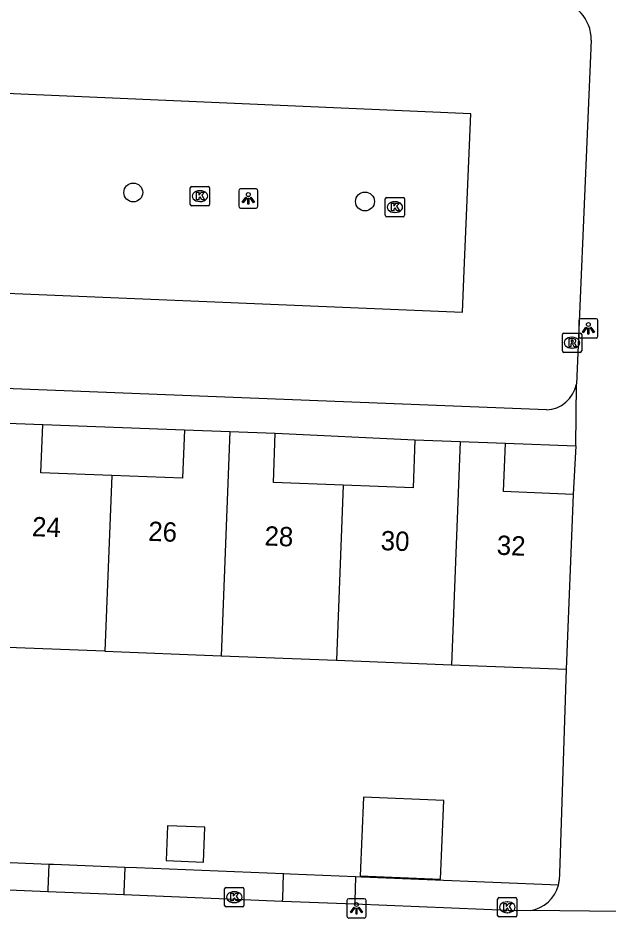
# Model space of a CAD drawing. Extents: x 160787 to 161428, y 386828 to 387483.
# Drawn here: x 161073.29 to 161103.85, y 387265 to 387311.59 of the extents above; entities that cross this region are included whole.
import ezdxf

# ---------------------------------------------------------------- set-up
doc = ezdxf.new("R2010")
doc.units = 0
for name, color, linetype in [('IMGEO_Boom', 7, 'Continuous'), ('IMGEO_Groenvoorziening', 7, 'Continuous'), ('IMGEO_Kolk', 7, 'Continuous'), ('IMGEO_Lichtpunt', 7, 'Continuous'), ('IMGEO_Pand', 7, 'Continuous'), ('IMGEO_Pand_nummerreeks', 7, 'Continuous'), ('IMGEO_Rioolput', 7, 'Continuous'), ('IMGEO_Voetpad_open', 7, 'Continuous')]:
    doc.layers.add(name, color=color, linetype=linetype)

msp = doc.modelspace()

# ---------------------------------------------------------------- linework, layer by layer
at = {"layer": 'IMGEO_Boom'}
for centre in [(161079.26, 387302.556), (161091.262, 387302.089)]:
    msp.add_circle(centre, 0.489, dxfattribs=at)
at = {"layer": 'IMGEO_Groenvoorziening'}
for points in [[(161074.883, 387267.773), (161070.863, 387267.936)], [(161087.049, 387267.279), (161079.434, 387267.588), (161078.824, 387267.613)], [(161101.28, 387266.701), (161091.074, 387267.115), (161090.777, 387267.127)]]:
    msp.add_lwpolyline(points, dxfattribs=at)
at = {"layer": 'IMGEO_Kolk'}
for p, q in [((161082.286, 387302.867), (161083.138, 387302.867)), ((161082.211, 387301.941), (161082.211, 387302.793)), ((161082.699, 387302.647), (161082.724, 387302.647)), ((161083.212, 387302.793), (161083.212, 387301.941)), ((161082.722, 387302.087), (161082.697, 387302.087)), ((161092.311, 387301.373), (161092.311, 387302.225)), ((161092.386, 387302.299), (161093.238, 387302.299)), ((161092.799, 387302.079), (161092.824, 387302.079)), ((161093.312, 387302.225), (161093.312, 387301.373)), ((161083.138, 387301.867), (161082.286, 387301.867)), ((161092.822, 387301.519), (161092.797, 387301.519)), ((161093.238, 387301.299), (161092.386, 387301.299)), ((161083.992, 387265.653), (161083.992, 387266.505)), ((161084.067, 387266.579), (161084.919, 387266.579)), ((161084.993, 387266.505), (161084.993, 387265.653)), ((161084.48, 387266.359), (161084.505, 387266.359)), ((161098.209, 387266.053), (161099.061, 387266.053)), ((161084.919, 387265.579), (161084.067, 387265.579)), ((161084.503, 387265.799), (161084.478, 387265.799)), ((161098.134, 387265.127), (161098.134, 387265.979)), ((161098.622, 387265.833), (161098.647, 387265.833)), ((161099.135, 387265.979), (161099.135, 387265.127)), ((161098.645, 387265.273), (161098.62, 387265.273)), ((161099.061, 387265.053), (161098.209, 387265.053))]:
    msp.add_line(p, q, dxfattribs=at)
for points in [[(161082.286, 387302.867), (161083.138, 387302.867)], [(161082.211, 387301.941), (161082.211, 387302.793)], [(161082.532, 387302.567), (161082.655, 387302.567), (161082.655, 387302.416), (161082.785, 387302.567), (161082.949, 387302.567), (161082.803, 387302.416), (161082.956, 387302.167), (161082.804, 387302.167), (161082.719, 387302.331), (161082.655, 387302.264), (161082.655, 387302.167), (161082.532, 387302.167), (161082.532, 387302.567)], [(161083.212, 387302.793), (161083.212, 387301.941)], [(161092.311, 387301.373), (161092.311, 387302.225)], [(161092.386, 387302.299), (161093.238, 387302.299)], [(161092.632, 387301.999), (161092.755, 387301.999), (161092.755, 387301.848), (161092.885, 387301.999), (161093.049, 387301.999), (161092.903, 387301.848), (161093.056, 387301.599), (161092.904, 387301.599), (161092.819, 387301.763), (161092.755, 387301.696), (161092.755, 387301.599), (161092.632, 387301.599), (161092.632, 387301.999)], [(161093.312, 387302.225), (161093.312, 387301.373)], [(161083.138, 387301.867), (161082.286, 387301.867)], [(161093.238, 387301.299), (161092.386, 387301.299)], [(161083.992, 387265.653), (161083.992, 387266.505)], [(161084.067, 387266.579), (161084.919, 387266.579)], [(161084.993, 387266.505), (161084.993, 387265.653)], [(161084.313, 387266.279), (161084.436, 387266.279), (161084.436, 387266.128), (161084.566, 387266.279), (161084.73, 387266.279), (161084.584, 387266.128), (161084.737, 387265.879), (161084.585, 387265.879), (161084.5, 387266.043), (161084.436, 387265.976), (161084.436, 387265.879), (161084.313, 387265.879), (161084.313, 387266.279)], [(161098.209, 387266.053), (161099.061, 387266.053)], [(161084.919, 387265.579), (161084.067, 387265.579)], [(161098.134, 387265.127), (161098.134, 387265.979)], [(161098.455, 387265.753), (161098.578, 387265.753), (161098.578, 387265.602), (161098.708, 387265.753), (161098.872, 387265.753), (161098.726, 387265.602), (161098.879, 387265.353), (161098.727, 387265.353), (161098.642, 387265.517), (161098.578, 387265.45), (161098.578, 387265.353), (161098.455, 387265.353), (161098.455, 387265.753)], [(161099.135, 387265.979), (161099.135, 387265.127)], [(161099.061, 387265.053), (161098.209, 387265.053)]]:
    msp.add_lwpolyline(points, dxfattribs=at)
for centre, start, end in [((161082.288, 387302.791), 91.552, 178.448), ((161082.288, 387302.791), 91.552, 178.448), ((161083.136, 387302.791), 1.552, 88.448), ((161083.136, 387302.791), 1.552, 88.448), ((161082.288, 387301.943), 181.552, 268.448), ((161082.288, 387301.943), 181.552, 268.448), ((161083.136, 387301.943), 271.552, 358.448), ((161083.136, 387301.943), 271.552, 358.448), ((161092.388, 387302.223), 91.552, 178.448), ((161092.388, 387302.223), 91.552, 178.448), ((161093.236, 387302.223), 1.552, 88.448), ((161093.236, 387302.223), 1.552, 88.448), ((161092.388, 387301.375), 181.552, 268.448), ((161092.388, 387301.375), 181.552, 268.448), ((161093.236, 387301.375), 271.552, 358.448), ((161093.236, 387301.375), 271.552, 358.448), ((161084.069, 387266.503), 91.552, 178.448), ((161084.069, 387266.503), 91.552, 178.448), ((161084.917, 387266.503), 1.552, 88.448), ((161084.917, 387266.503), 1.552, 88.448), ((161098.211, 387265.977), 91.552, 178.448), ((161098.211, 387265.977), 91.552, 178.448), ((161099.059, 387265.977), 1.552, 88.448), ((161099.059, 387265.977), 1.552, 88.448), ((161084.069, 387265.655), 181.552, 268.448), ((161084.069, 387265.655), 181.552, 268.448), ((161084.917, 387265.655), 271.552, 358.448), ((161084.917, 387265.655), 271.552, 358.448), ((161098.211, 387265.129), 181.552, 268.448), ((161098.211, 387265.129), 181.552, 268.448), ((161099.059, 387265.129), 271.552, 358.448), ((161099.059, 387265.129), 271.552, 358.448)]:
    msp.add_arc(centre, 0.0765, start, end, dxfattribs=at)
for centre, major_axis, ratio, start_param, end_param in [((161082.698, 387302.367), (-0.387, 0.002), 0.722429, 4.712389, 7.853982), ((161082.723, 387302.367), (-0.39, 0.002), 0.717154, 1.570796, 4.712389), ((161092.798, 387301.799), (-0.387, 0.002), 0.722429, 4.712389, 7.853982), ((161092.823, 387301.799), (-0.39, 0.002), 0.717154, 1.570796, 4.712389), ((161084.479, 387266.079), (-0.387, 0.002), 0.722429, 4.712389, 7.853982), ((161084.504, 387266.079), (-0.39, 0.002), 0.717154, 1.570796, 4.712389), ((161098.621, 387265.553), (-0.387, 0.002), 0.722429, 4.712389, 7.853982), ((161098.646, 387265.553), (-0.39, 0.002), 0.717154, 1.570796, 4.712389)]:
    msp.add_ellipse(centre, major_axis=major_axis, ratio=ratio, start_param=start_param, end_param=end_param, dxfattribs=at)
at = {"layer": 'IMGEO_Lichtpunt'}
for p, q in [((161084.72, 387302.649), (161084.72, 387301.842)), ((161084.72, 387302.649), (161084.72, 387301.842)), ((161085.622, 387302.744), (161084.814, 387302.744)), ((161085.622, 387302.744), (161084.814, 387302.744)), ((161085.716, 387301.842), (161085.716, 387302.649)), ((161085.716, 387301.842), (161085.716, 387302.649)), ((161084.814, 387301.748), (161085.622, 387301.748)), ((161084.814, 387301.748), (161085.622, 387301.748)), ((161102.335, 387295.924), (161102.335, 387295.117)), ((161102.335, 387295.924), (161102.335, 387295.117)), ((161103.237, 387296.019), (161102.429, 387296.019)), ((161103.237, 387296.019), (161102.429, 387296.019)), ((161103.331, 387295.117), (161103.331, 387295.924)), ((161103.331, 387295.117), (161103.331, 387295.924)), ((161102.429, 387295.023), (161103.237, 387295.023)), ((161102.429, 387295.023), (161103.237, 387295.023)), ((161091.227, 387265.995), (161090.419, 387265.995)), ((161091.227, 387265.995), (161090.419, 387265.995)), ((161090.325, 387265.9), (161090.325, 387265.093)), ((161090.325, 387265.9), (161090.325, 387265.093)), ((161091.321, 387265.093), (161091.321, 387265.9)), ((161091.321, 387265.093), (161091.321, 387265.9)), ((161090.419, 387264.999), (161091.227, 387264.999)), ((161090.419, 387264.999), (161091.227, 387264.999))]:
    msp.add_line(p, q, dxfattribs=at)
for points in [[(161085.094, 387302.313), (161085.133, 387302.285), (161084.945, 387302.023), (161084.907, 387302.05), (161085.094, 387302.313)], [(161085.196, 387302.265), (161085.243, 387302.265), (161085.243, 387301.943), (161085.196, 387301.943), (161085.196, 387302.265)], [(161085.306, 387302.285), (161085.344, 387302.312), (161085.531, 387302.05), (161085.492, 387302.022), (161085.306, 387302.285)], [(161102.709, 387295.588), (161102.748, 387295.56), (161102.56, 387295.298), (161102.522, 387295.325), (161102.709, 387295.588)], [(161102.811, 387295.54), (161102.858, 387295.54), (161102.858, 387295.218), (161102.811, 387295.218), (161102.811, 387295.54)], [(161102.921, 387295.56), (161102.959, 387295.587), (161103.146, 387295.325), (161103.107, 387295.297), (161102.921, 387295.56)], [(161090.699, 387265.564), (161090.738, 387265.536), (161090.55, 387265.274), (161090.512, 387265.301), (161090.699, 387265.564)], [(161090.911, 387265.536), (161090.949, 387265.563), (161091.136, 387265.301), (161091.097, 387265.273), (161090.911, 387265.536)], [(161090.801, 387265.516), (161090.848, 387265.516), (161090.848, 387265.194), (161090.801, 387265.194), (161090.801, 387265.516)]]:
    msp.add_lwpolyline(points, dxfattribs=at)
for centre in [(161085.219, 387302.447), (161102.834, 387295.722), (161090.824, 387265.698)]:
    msp.add_circle(centre, 0.0994, dxfattribs=at)
for centre, start, end in [((161084.814, 387302.649), 90, 180), ((161084.814, 387302.649), 90, 180), ((161085.622, 387302.649), 0, 90), ((161085.622, 387302.649), 0, 90), ((161084.814, 387301.842), 180, 270), ((161084.814, 387301.842), 180, 270), ((161085.622, 387301.842), 270, 0), ((161085.622, 387301.842), 270, 360), ((161102.429, 387295.924), 90, 180), ((161102.429, 387295.924), 90, 180), ((161103.237, 387295.924), 0, 90), ((161103.237, 387295.924), 0, 90), ((161102.429, 387295.117), 180, 270), ((161102.429, 387295.117), 180, 270), ((161103.237, 387295.117), 270, 0), ((161103.237, 387295.117), 270, 360), ((161090.419, 387265.9), 90, 180), ((161090.419, 387265.9), 90, 180), ((161091.227, 387265.9), 0, 90), ((161091.227, 387265.9), 0, 90), ((161090.419, 387265.093), 180, 270), ((161090.419, 387265.093), 180, 270), ((161091.227, 387265.093), 270, 0), ((161091.227, 387265.093), 270, 360)]:
    msp.add_arc(centre, 0.0946, start, end, dxfattribs=at)
at = {"layer": 'IMGEO_Pand'}
for points in [[(161072.26, 387290.639), (161074.568, 387290.549)], [(161078.142, 387287.905), (161074.471, 387288.048), (161074.568, 387290.549)], [(161081.915, 387290.273), (161081.817, 387287.761), (161078.142, 387287.905)], [(161081.915, 387290.273), (161084.265, 387290.182)], [(161084.265, 387290.182), (161083.812, 387278.572)], [(161084.265, 387290.182), (161086.617, 387290.09)], [(161090.135, 387287.403), (161086.518, 387287.544), (161086.617, 387290.09)], [(161093.847, 387289.756), (161093.75, 387287.262), (161090.135, 387287.403)], [(161093.847, 387289.756), (161096.19, 387289.665)], [(161096.19, 387289.665), (161095.739, 387278.107)], [(161096.19, 387289.665), (161098.533, 387289.573)], [(161102.045, 387286.93), (161098.436, 387287.071), (161098.533, 387289.573)], [(161078.142, 387287.905), (161077.787, 387278.807)], [(161090.135, 387287.403), (161089.782, 387278.339)], [(161102.045, 387286.93), (161101.692, 387277.875)], [(161077.787, 387278.807), (161071.808, 387279.04)], [(161077.787, 387278.807), (161083.812, 387278.572)], [(161083.812, 387278.572), (161089.782, 387278.339)], [(161089.782, 387278.339), (161095.739, 387278.107)], [(161095.739, 387278.107), (161101.692, 387277.875)], [(161091.014, 387267.179), (161095.178, 387267.009), (161095.344, 387271.089), (161091.18, 387271.259), (161091.014, 387267.179)], [(161080.967, 387267.968), (161082.892, 387267.893), (161082.962, 387269.703), (161081.037, 387269.778), (161080.967, 387267.968)]]:
    msp.add_lwpolyline(points, dxfattribs=at)
at = {"layer": 'IMGEO_Rioolput'}
for p, q in [((161101.488, 387294.354), (161101.488, 387295.206)), ((161101.563, 387295.28), (161102.415, 387295.28)), ((161101.976, 387295.06), (161102.001, 387295.06)), ((161102.489, 387295.206), (161102.489, 387294.354)), ((161101.999, 387294.5), (161101.974, 387294.5)), ((161102.415, 387294.28), (161101.563, 387294.28))]:
    msp.add_line(p, q, dxfattribs=at)
for points in [[(161101.488, 387294.354), (161101.488, 387295.206)], [(161101.563, 387295.28), (161102.415, 387295.28)], [(161102.077, 387294.978), (161101.825, 387294.98), (161101.825, 387294.58)], [(161102.003, 387294.899), (161101.949, 387294.899), (161101.949, 387294.818)], [(161102.489, 387295.206), (161102.489, 387294.354)], [(161101.825, 387294.58), (161101.949, 387294.58), (161101.949, 387294.742), (161101.96, 387294.742)], [(161101.949, 387294.818), (161102.001, 387294.818)], [(161102.007, 387294.713), (161102.078, 387294.58), (161102.218, 387294.58), (161102.153, 387294.706)], [(161102.415, 387294.28), (161101.563, 387294.28)]]:
    msp.add_lwpolyline(points, dxfattribs=at)
for centre, radius, start, end in [((161101.565, 387295.204), 0.0765, 91.552, 178.448), ((161101.565, 387295.204), 0.0765, 91.552, 178.448), ((161102.009, 387294.803), 0.0964, 77.0061, 93.1865), ((161102.023, 387294.86), 0.0378, 276.6634, 79.6772), ((161102.076, 387294.868), 0.109, 350.3612, 89.416), ((161102.413, 387295.204), 0.0765, 1.552, 88.448), ((161102.413, 387295.204), 0.0765, 1.552, 88.448), ((161101.959, 387294.689), 0.0533, 26.0293, 88.6989), ((161101.985, 387295.007), 0.19, 274.7715, 282.9687), ((161102.074, 387294.868), 0.112, 277.5842, 350.9817), ((161102.058, 387294.653), 0.108, 29.5134, 73.7905), ((161101.565, 387294.356), 0.0765, 181.552, 268.448), ((161101.565, 387294.356), 0.0765, 181.552, 268.448), ((161102.413, 387294.356), 0.0765, 271.552, 358.448), ((161102.413, 387294.356), 0.0765, 271.552, 358.448)]:
    msp.add_arc(centre, radius, start, end, dxfattribs=at)
for centre, major_axis, ratio, start_param, end_param in [((161101.975, 387294.78), (-0.387, 0.002), 0.722429, 4.712389, 7.853982), ((161102, 387294.78), (-0.39, 0.002), 0.717154, 1.570796, 4.712389)]:
    msp.add_ellipse(centre, major_axis=major_axis, ratio=ratio, start_param=start_param, end_param=end_param, dxfattribs=at)
at = {"layer": 'IMGEO_Voetpad_open'}
for points in [[(161102.976, 387310.447), (161102.212, 387292.628)], [(161096.75, 387306.632), (161049.733, 387308.677), (161049.512, 387308.687), (161049.17, 387300.494), (161049.08, 387298.333), (161096.316, 387296.364), (161096.407, 387298.525), (161096.75, 387306.632)], [(161100.662, 387291.305), (161033.559, 387293.946)], [(161102.179, 387289.436), (161102.212, 387292.628)], [(161074.568, 387290.549), (161081.915, 387290.273)], [(161086.617, 387290.09), (161093.847, 387289.756)], [(161098.533, 387289.573), (161102.179, 387289.436)], [(161102.179, 387289.436), (161102.045, 387286.93)], [(161101.692, 387277.875), (161101.339, 387267.305), (161101.327, 387266.961)], [(161074.883, 387267.773), (161074.832, 387266.481), (161074.828, 387266.36)], [(161078.824, 387267.613), (161075.127, 387267.763), (161074.883, 387267.773)], [(161078.824, 387267.613), (161078.774, 387266.328), (161078.768, 387266.198)], [(161086.994, 387265.86), (161086.999, 387266.008), (161087.049, 387267.279)], [(161090.777, 387267.127), (161087.387, 387267.265), (161087.049, 387267.279)], [(161090.777, 387267.127), (161090.728, 387265.863), (161090.722, 387265.707)], [(161074.828, 387266.36), (161067.122, 387266.676)], [(161078.768, 387266.198), (161074.828, 387266.36)], [(161086.994, 387265.86), (161078.768, 387266.198)], [(161090.722, 387265.707), (161086.994, 387265.86)], [(161099.828, 387265.381), (161099.086, 387265.364), (161090.722, 387265.707)], [(161104.419, 387265.337), (161099.828, 387265.381)]]:
    msp.add_lwpolyline(points, dxfattribs=at)
for centre, radius, start, end in [((161100.953, 387310.487), 2.024, 358.8545, 86.85), ((161100.618, 387292.926), 1.621, 271.5467, 349.418), ((161099.442, 387267.168), 1.897, 345.7595, 353.7471), ((161099.547, 387267.148), 1.79, 279.0246, 345.5228)]:
    msp.add_arc(centre, radius, start, end, dxfattribs=at)

# ---------------------------------------------------------------- texts
at = {"layer": 'IMGEO_Pand_nummerreeks'}
for s, p in [('24', (161074, 387284.768)), ('26', (161080.02, 387284.528)), ('28', (161086.042, 387284.287)), ('30', (161092.062, 387284.046)), ('32', (161098.075, 387283.806))]:
    msp.add_text(s, height=1, rotation=357.7109, dxfattribs=at).set_placement(p)

doc.saveas('drawing.dxf')
